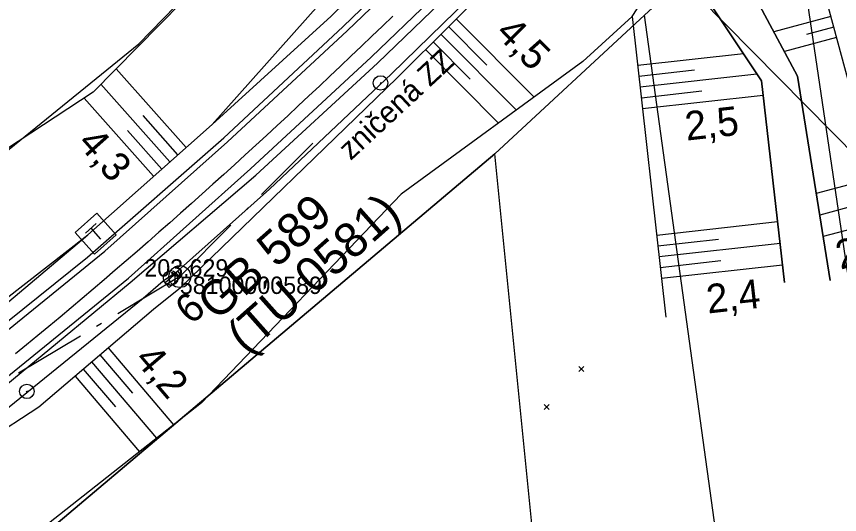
# Model space of a CAD drawing. Extents: x -800194 to -799078, y -1007177 to -1006597.
# Drawn here: x -799466.4 to -799409.6, y -1006941.3 to -1006906.9 of the extents above; entities that cross this region are included whole.
import ezdxf

# ---------------------------------------------------------------- set-up
doc = ezdxf.new("R2010")
doc.units = 0
for name, color, linetype in [('02_Osa_koleje', 7, 'Continuous'), ('Vrstva 11', 7, 'Continuous'), ('Vrstva 12', 7, 'Continuous'), ('Vrstva 33', 7, 'Continuous'), ('Vrstva 4', 7, 'Continuous'), ('Vrstva 48', 7, 'Continuous'), ('Vrstva 49', 7, 'Continuous'), ('Vrstva 5', 7, 'Continuous'), ('Vrstva 50', 7, 'Continuous'), ('Vrstva 53', 7, 'Continuous'), ('Vrstva 55', 7, 'Continuous'), ('Vrstva 60', 7, 'Continuous'), ('Vrstva 61', 7, 'Continuous'), ('Vrstva 63', 7, 'Continuous'), ('Vrstva 7', 7, 'Continuous')]:
    doc.layers.add(name, color=color, linetype=linetype)

msp = doc.modelspace()

# ---------------------------------------------------------------- linework, layer by layer
at = {"layer": '02_Osa_koleje'}
msp.add_lwpolyline([(-799440.449, -1006906.887), (-799441.17, -1006907.581), (-799441.891, -1006908.273), (-799442.614, -1006908.965), (-799443.338, -1006909.655), (-799444.063, -1006910.343), (-799444.789, -1006911.03), (-799445.517, -1006911.716), (-799446.246, -1006912.401), (-799446.976, -1006913.084), (-799447.708, -1006913.766), (-799448.441, -1006914.446), (-799449.175, -1006915.124), (-799449.911, -1006915.802), (-799450.649, -1006916.477), (-799451.388, -1006917.151), (-799452.128, -1006917.823), (-799452.87, -1006918.493), (-799453.614, -1006919.162), (-799454.359, -1006919.828), (-799455.106, -1006920.493), (-799455.855, -1006921.156), (-799456.605, -1006921.818), (-799457.357, -1006922.477), (-799458.111, -1006923.134), (-799458.866, -1006923.789), (-799459.623, -1006924.442), (-799460.382, -1006925.093), (-799461.143, -1006925.742), (-799461.906, -1006926.389), (-799462.671, -1006927.033), (-799463.437, -1006927.675), (-799464.206, -1006928.315), (-799464.976, -1006928.953), (-799465.749, -1006929.588), (-799466.523, -1006930.22)], dxfattribs=at)
at = {"layer": 'Vrstva 11'}
for p, q in [((-799455.418, -1006924.635), (-799456.17, -1006925.303)), ((-799455.51, -1006925.383), (-799455.47, -1006924.681)), ((-799455.891, -1006925.459), (-799455.866, -1006925.033))]:
    msp.add_line(p, q, dxfattribs=at)
msp.add_circle((-799455.794, -1006924.969), 0.503, dxfattribs=at)
msp.add_arc((-799455.794, -1006924.969), 0.503, 221.618, 41.618, dxfattribs=at)
at = {"layer": 'Vrstva 12'}
msp.add_lwpolyline([(-799455.328, -1006924.513), (-799455.013, -1006924.859), (-799455.894, -1006925.627), (-799456.318, -1006925.174), (-799455.328, -1006924.513)], dxfattribs=at)
at = {"layer": 'Vrstva 33'}
for p, q in [((-799461.686, -1006921.876), (-799460.938, -1006921.212)), ((-799461.312, -1006921.544), (-799460.648, -1006922.292))]:
    msp.add_line(p, q, dxfattribs=at)
msp.add_lwpolyline([(-799462.392, -1006921.835), (-799460.897, -1006920.506), (-799459.568, -1006922.001), (-799461.063, -1006923.33), (-799462.392, -1006921.835)], dxfattribs=at)
at = {"layer": 'Vrstva 4'}
for points in [[(-799510.394, -1006958.536), (-799498.027, -1006951.328), (-799477.988, -1006937.435), (-799460.33, -1006923.117), (-799451.862, -1006915.581), (-799443.604, -1006907.9), (-799435.444, -1006900.067), (-799428.64, -1006893.299), (-799422.817, -1006887.511), (-799415.998, -1006880.595), (-799408.158, -1006872.652), (-799401.02, -1006864.85)], [(-799509.248, -1006960.724), (-799497.456, -1006953.809), (-799476.495, -1006939.437), (-799458.707, -1006924.982), (-799450.277, -1006917.43), (-799441.932, -1006909.717), (-799433.783, -1006901.867), (-799426.9, -1006895.092), (-799421.037, -1006889.182), (-799414.218, -1006882.281), (-799406.443, -1006874.417), (-799398.609, -1006866.93)], [(-799511.236, -1006957.129), (-799499.236, -1006950.771), (-799498.598, -1006949.914), (-799498.679, -1006949.705), (-799496.151, -1006948.479), (-799496.251, -1006948.258), (-799490.687, -1006944.683), (-799490.497, -1006944.878), (-799488.249, -1006943.052), (-799488.105, -1006943.216), (-799486.269, -1006941.68), (-799478.997, -1006936.484), (-799474.568, -1006932.916), (-799474.237, -1006932.694), (-799461.519, -1006921.99), (-799452.935, -1006914.372), (-799444.695, -1006906.886), (-799436.579, -1006898.932), (-799429.629, -1006892.192), (-799429.07, -1006892.727), (-799423.479, -1006886.901), (-799416.56, -1006880.007), (-799417.085, -1006879.46), (-799415.349, -1006878.386)], [(-799510.726, -1006958.045), (-799497.901, -1006950.516), (-799478.36, -1006937.055), (-799461.534, -1006923.53), (-799452.128, -1006915.305), (-799443.894, -1006907.632), (-799435.739, -1006899.754), (-799428.922, -1006893.007), (-799423.223, -1006887.256), (-799416.277, -1006880.269), (-799414.896, -1006878.87)], [(-799509.087, -1006961.127), (-799497.277, -1006954.118), (-799476.183, -1006939.802), (-799458.586, -1006925.284), (-799449.914, -1006917.869), (-799441.499, -1006910.139), (-799433.371, -1006902.28), (-799426.451, -1006895.478), (-799420.657, -1006889.585), (-799413.85, -1006882.742), (-799412.388, -1006881.287)], [(-799475.489, -1006940.774), (-799457.684, -1006926.366), (-799456.318, -1006925.174), (-799455.328, -1006924.513), (-799448.961, -1006918.843), (-799440.534, -1006910.864), (-799432.566, -1006903.097), (-799428.918, -1006899.95), (-799428.131, -1006899.117), (-799425.824, -1006895.981), (-799426.173, -1006895.627), (-799420.283, -1006889.914), (-799413.647, -1006882.957), (-799413.271, -1006883.261), (-799411.693, -1006881.939)]]:
    msp.add_lwpolyline(points, dxfattribs=at)
at = {"layer": 'Vrstva 48'}
for p, q in [((-799436.07, -1006907.081), (-799430.681, -1006912.486)), ((-799410.183, -1006906.916), (-799414.124, -1006907.981)), ((-799436.601, -1006907.611), (-799433.948, -1006910.272)), ((-799409.987, -1006907.64), (-799411.874, -1006908.15)), ((-799437.132, -1006908.141), (-799431.908, -1006913.38)), ((-799437.663, -1006908.67), (-799435.092, -1006911.248)), ((-799409.792, -1006908.364), (-799413.398, -1006909.338)), ((-799438.194, -1006909.2), (-799433.135, -1006914.274)), ((-799423.526, -1006910.286), (-799416.226, -1006909.471)), ((-799454.726, -1006915.962), (-799459.558, -1006910.517)), ((-799423.443, -1006911.031), (-799419.601, -1006910.602)), ((-799423.36, -1006911.777), (-799415.291, -1006910.876)), ((-799455.848, -1006916.957), (-799460.612, -1006911.589)), ((-799423.277, -1006912.522), (-799419.11, -1006912.057)), ((-799456.97, -1006917.953), (-799461.771, -1006912.543)), ((-799423.193, -1006913.268), (-799414.858, -1006912.337)), ((-799455.287, -1006916.459), (-799457.686, -1006913.756)), ((-799456.409, -1006917.455), (-799458.774, -1006914.79)), ((-799407.172, -1006918.053), (-799411.191, -1006919.139)), ((-799406.781, -1006919.501), (-799410.952, -1006920.628)), ((-799422.218, -1006922.007), (-799413.866, -1006921.075)), ((-799406.389, -1006920.949), (-799410.713, -1006922.118)), ((-799422.135, -1006922.753), (-799417.958, -1006922.286)), ((-799422.051, -1006923.498), (-799413.697, -1006922.565)), ((-799421.968, -1006924.243), (-799417.79, -1006923.777)), ((-799421.885, -1006924.989), (-799413.528, -1006924.056)), ((-799460.115, -1006929.802), (-799455.59, -1006935.113)), ((-799460.686, -1006930.288), (-799458.433, -1006932.933)), ((-799461.257, -1006930.774), (-799456.769, -1006936.043)), ((-799461.828, -1006931.261), (-799459.593, -1006933.884)), ((-799462.399, -1006931.747), (-799457.948, -1006936.972))]:
    msp.add_line(p, q, dxfattribs=at)
at = {"layer": 'Vrstva 49'}
for p, q in [((-799423.903, -1006906.911), (-799421.584, -1006927.684)), ((-799427.607, -1006931.077), (-799427.253, -1006931.431)), ((-799427.607, -1006931.431), (-799427.253, -1006931.077)), ((-799429.993, -1006933.713), (-799429.639, -1006934.067)), ((-799429.993, -1006934.067), (-799429.639, -1006933.713))]:
    msp.add_line(p, q, dxfattribs=at)
for points in [[(-799410.227, -1006925.149), (-799412.491, -1006911.033), (-799419.106, -1006898.668), (-799423.582, -1006889.778), (-799429.735, -1006878.378), (-799431.818, -1006855.328)], [(-799426.038, -1006858.234), (-799426.419, -1006863.568), (-799427.212, -1006869.673), (-799426.968, -1006870.003), (-799426.4, -1006870.552), (-799426.115, -1006870.824), (-799426.018, -1006877.519), (-799424.103, -1006883.903), (-799422.705, -1006885.358), (-799423.751, -1006886.402), (-799420.096, -1006889.979), (-799419.086, -1006888.964), (-799412.022, -1006900.113), (-799405.487, -1006924.286)], [(-799429.125, -1006891.656), (-799433.133, -1006889.484), (-799437.572, -1006888.963), (-799439.693, -1006890.332), (-799461.15, -1006912.135), (-799487.142, -1006929.222), (-799487.006, -1006931.546), (-799490.308, -1006935.771)], [(-799490.09, -1006944.145), (-799488.194, -1006942.597), (-799488.011, -1006942.815), (-799488.011, -1006942.815), (-799486.419, -1006941.508), (-799486.269, -1006941.68), (-799484.618, -1006939.109), (-799474.926, -1006932.405), (-799474.596, -1006932.171), (-799461.519, -1006921.99), (-799452.935, -1006914.372), (-799445.566, -1006906.106), (-799432.588, -1006892.596), (-799429.125, -1006891.656)], [(-799486.865, -1006949.018), (-799484.86, -1006947.727), (-799485.016, -1006947.459), (-799485.713, -1006947.881), (-799483.734, -1006946.536), (-799483.686, -1006946.569), (-799483.396, -1006947.063), (-799482.389, -1006946.51), (-799482.647, -1006946.068), (-799475.489, -1006940.774), (-799464.892, -1006933.871), (-799456.989, -1006927.138), (-799455.117, -1006925.642), (-799440.165, -1006911.165), (-799428.918, -1006899.95), (-799428.299, -1006900.544), (-799427.466, -1006899.73), (-799428.131, -1006899.117), (-799426.509, -1006898.237), (-799425.17, -1006895.342)], [(-799413.387, -1006925.296), (-799414.969, -1006911.36), (-799421.688, -1006901.262)], [(-799423.903, -1006906.911), (-799421.655, -1006903.434)], [(-799423.903, -1006906.911), (-799427.313, -1006910.033), (-799439.866, -1006919.177), (-799453.667, -1006933.596), (-799478.523, -1006953.199), (-799482.72, -1006952.931), (-799486.865, -1006949.018)]]:
    msp.add_lwpolyline(points, dxfattribs=at)
at = {"layer": 'Vrstva 5'}
msp.add_line((-799389.844, -1006935.446), (-799426.915, -1006897.844), dxfattribs=at)
at = {"layer": 'Vrstva 50'}
msp.add_line((-799441.33, -1006911.537), (-799441.256, -1006911.469), dxfattribs=at)
for points in [[(-799431.818, -1006855.328), (-799429.735, -1006878.378), (-799423.582, -1006889.778), (-799419.106, -1006898.668), (-799412.491, -1006911.033), (-799410.227, -1006925.149)], [(-799433.824, -1006862.471), (-799432.369, -1006880.085), (-799427.694, -1006890.471), (-799424.101, -1006893.992), (-799424.223, -1006894.144), (-799421.688, -1006901.262), (-799414.969, -1006911.36), (-799413.387, -1006925.296)]]:
    msp.add_lwpolyline(points, dxfattribs=at)
msp.add_circle((-799441.293, -1006911.503), 0.5, dxfattribs=at)
at = {"layer": 'Vrstva 53'}
for points in [[(-799559.64, -1006968.48), (-799519.68, -1006952.01), (-799500.87, -1006940.41), (-799496.64, -1006937.8), (-799494.85, -1006936.7), (-799484.519, -1006930.319), (-799457.99, -1006908.8), (-799435, -1006885.17), (-799430.26, -1006880.27), (-799425.53, -1006875.38), (-799422.55, -1006864.36), (-799390.88, -1006834), (-799358.35, -1006806.65), (-799352.29, -1006801.56), (-799330.91, -1006783.58), (-799314.235, -1006766.649)], [(-799312.398, -1006791.976), (-799331.37, -1006811.87), (-799413.75, -1006898.23), (-799418.41, -1006902.53), (-799423.07, -1006906.83), (-799433.4, -1006916.39), (-799469.5, -1006946.86), (-799487.22, -1006958.47), (-799495.25, -1006963.74), (-799521.98, -1006977.8), (-799546.71, -1006987.83)]]:
    msp.add_lwpolyline(points, dxfattribs=at)
at = {"layer": 'Vrstva 55'}
for p, q in [((-799433.4, -1006916.39), (-799423.07, -1006906.83)), ((-799424.1, -1007009.73), (-799433.4, -1006916.39))]:
    msp.add_line(p, q, dxfattribs=at)
for points in [[(-799494.85, -1006936.7), (-799484.52, -1006930.32), (-799457.99, -1006908.8), (-799435, -1006885.17)], [(-799413.75, -1006898.23), (-799411.99, -1006904.75), (-799406.72, -1006940.36), (-799397.01, -1006988.73)], [(-799410.89, -1007000.14), (-799412.5, -1006983.38), (-799423.07, -1006906.83)], [(-799487.22, -1006958.47), (-799469.5, -1006946.86), (-799433.4, -1006916.39)]]:
    msp.add_lwpolyline(points, dxfattribs=at)
at = {"layer": 'Vrstva 60'}
msp.add_line((-799455.158, -1006924.878), (-799455.158, -1006924.878), dxfattribs=at)
at = {"layer": 'Vrstva 63'}
for p, q in [((-799449.511, -1006919.212), (-799445.981, -1006915.67)), ((-799450.711, -1006920.416), (-799450.428, -1006920.132)), ((-799455.158, -1006924.878), (-799451.628, -1006921.336)), ((-799455.158, -1006924.878), (-799459.448, -1006927.447)), ((-799455.195, -1006924.911), (-799455.121, -1006924.845)), ((-799460.563, -1006928.115), (-799460.906, -1006928.321)), ((-799462.021, -1006928.988), (-799466.311, -1006931.558))]:
    msp.add_line(p, q, dxfattribs=at)
msp.add_circle((-799455.158, -1006924.878), 0.756, dxfattribs=at)
at = {"layer": 'Vrstva 7'}
msp.add_line((-799465.764, -1006932.836), (-799465.688, -1006932.772), dxfattribs=at)
msp.add_circle((-799465.726, -1006932.804), 0.5, dxfattribs=at)

# ---------------------------------------------------------------- texts
at = {"layer": 'Vrstva 11'}
msp.add_text('6', height=2, rotation=41.618, dxfattribs=at).set_placement((-799454.367, -1006928.264))
at = {"layer": 'Vrstva 48'}
for s, rotation, p in [('4,5', 314.9184, (-799433.431, -1006908.143)), ('2,5', 6.3699, (-799420.157, -1006915.489)), ('4,3', 311.5879, (-799462.304, -1006915.704)), ('2,3', 15.1279, (-799409.526, -1006924.407)), ('2,4', 6.3699, (-799418.675, -1006927.434)), ('4,2', 310.4295, (-799458.357, -1006930.642))]:
    msp.add_text(s, height=2, rotation=rotation, dxfattribs=at).set_placement(p)
at = {"layer": 'Vrstva 50'}
msp.add_text('zničená ZZ', height=1.5, rotation=42.8844, dxfattribs=at).set_placement((-799443.358, -1006916.901))
at = {"layer": 'Vrstva 60'}
msp.add_text('58100000589', height=1.2, dxfattribs=at).set_placement((-799455.158, -1006926.078))
at = {"layer": 'Vrstva 61'}
msp.add_text('203.629', height=1.2, dxfattribs=at).set_placement((-799457.612, -1006924.878))
at = {"layer": 'Vrstva 63'}
for s, p in [('GB 589', (-799452.612, -1006928.004)), ('(TÚ 0581)', (-799450.549, -1006930.326))]:
    msp.add_text(s, height=2.4, rotation=41.618, dxfattribs=at).set_placement(p)

doc.saveas('drawing.dxf')
